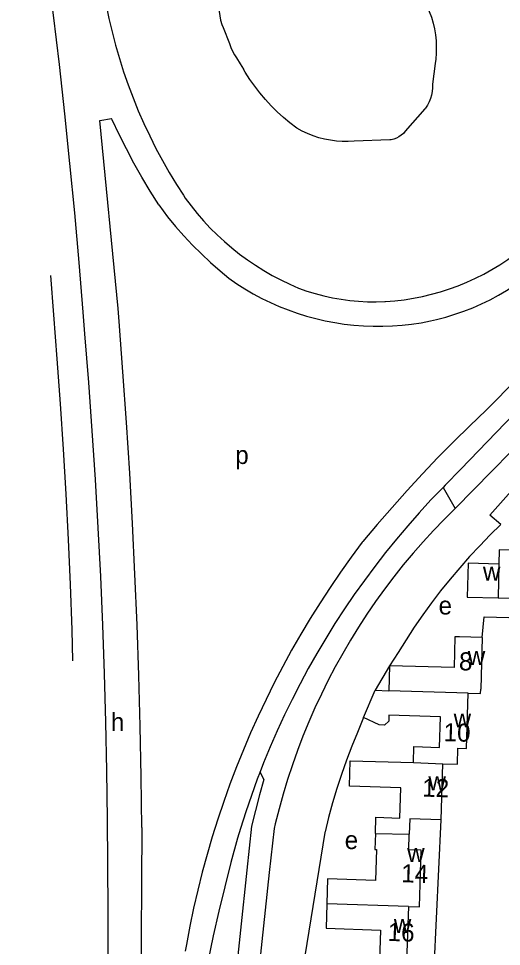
# Model space of a CAD drawing. Extents: x 161936 to 163647, y 386450 to 388633.
# Drawn here: x 162095.8 to 162202.6, y 388193.1 to 388398.4 of the extents above; entities that cross this region are included whole.
import ezdxf

# ---------------------------------------------------------------- set-up
doc = ezdxf.new("R2010")
doc.units = 0
for name, color, linetype in [('BLT_Basislijn', 7, 'Continuous'), ('BLT_Bebouwing', 7, 'Continuous'), ('BLT_Centroide', 7, 'Continuous'), ('BLT_Huisnummer', 7, 'Continuous'), ('BLT_Huisnummer_ tussenligend', 7, 'Continuous'), ('BLT_Onderverdeling_panden', 7, 'Continuous'), ('BLT_Vlakafsluiter', 7, 'Continuous')]:
    doc.layers.add(name, color=color, linetype=linetype)

msp = doc.modelspace()

# ---------------------------------------------------------------- linework, layer by layer
at = {"layer": 'BLT_Basislijn'}
for p, q in [((162141, 388396.47), (162142.43, 388392.92)), ((162187.94, 388388.47), (162187.36, 388383.94)), ((162185.66, 388378.42), (162181.32, 388373.49)), ((162177.93, 388371.59), (162170.03, 388371.27)), ((162132.22, 388359.34), (162132.63, 388358.72)), ((162126.77, 388357.19), (162128.69, 388354.54)), ((162215.83, 388321.82), (162193.61, 388298.7)), ((162206.52, 388295.81), (162200.04, 388288.54)), ((162202.51, 388286.46), (162200.04, 388288.54)), ((162150.04, 388230.05), (162149.21, 388231.74)), ((162187.39, 388181.56), (162189.26, 388221.14))]:
    msp.add_line(p, q, dxfattribs=at)
for points in [[(162095.76, 388453.7), (162097.45, 388442.82), (162099.06, 388431.93), (162100.59, 388421.03), (162102.04, 388410.11), (162103.42, 388399.19), (162104.71, 388388.26), (162105.92, 388377.32), (162107.06, 388366.37), (162108.11, 388355.41), (162109.09, 388344.45), (162109.98, 388333.48), (162110.35, 388328.63)], [(162114.11, 388407.51), (162114.58, 388404.48), (162115.12, 388401.46), (162115.74, 388398.46), (162116.44, 388395.47), (162117.21, 388392.51), (162118.07, 388389.56), (162119, 388386.64), (162120.01, 388383.75), (162121.09, 388380.88), (162122.24, 388378.04), (162123.47, 388375.23), (162124.78, 388372.45), (162126.15, 388369.71), (162127.6, 388367.01), (162129.11, 388364.35), (162130.7, 388361.72), (162132.22, 388359.34)], [(162184.87, 388403.57), (162185.53, 388402.42), (162186.13, 388401.22), (162186.65, 388399.99), (162187.1, 388398.73), (162187.48, 388397.44), (162187.77, 388396.14), (162187.99, 388394.82), (162188.13, 388393.49), (162188.19, 388392.15), (162188.17, 388390.81), (162188.07, 388389.48), (162187.94, 388388.47)], [(162140.1, 388400.92), (162140.14, 388399.96), (162140.26, 388399.01), (162140.46, 388398.07), (162140.74, 388397.15), (162141, 388396.47)], [(162142.43, 388392.92), (162142.73, 388392.05), (162143.09, 388391.21), (162143.54, 388390.4), (162143.97, 388389.74)], [(162143.97, 388389.74), (162144.81, 388388.42), (162145.5, 388387.2)], [(162157.32, 388374.18), (162155.82, 388375.33), (162154.38, 388376.54), (162152.99, 388377.81), (162151.66, 388379.14), (162150.38, 388380.52), (162149.16, 388381.96), (162148.01, 388383.44), (162146.92, 388384.98), (162145.89, 388386.56), (162145.5, 388387.2)], [(162187.36, 388383.94), (162187.36, 388383.12), (162187.29, 388382.31), (162187.13, 388381.51), (162186.9, 388380.73), (162186.6, 388379.97), (162186.22, 388379.25), (162185.77, 388378.57), (162185.66, 388378.42)], [(162117.77, 388334.29), (162113.78, 388375.91), (162116.32, 388376.3)], [(162126.77, 388357.19), (162124.88, 388360.23), (162123.05, 388363.31), (162121.3, 388366.43), (162119.61, 388369.59), (162118, 388372.79), (162116.45, 388376.02), (162116.32, 388376.3)], [(162170.03, 388371.27), (162168.71, 388371.2), (162167.4, 388371.22), (162166.08, 388371.31), (162164.78, 388371.49), (162163.49, 388371.74), (162162.21, 388372.07), (162160.96, 388372.48), (162159.73, 388372.96), (162158.54, 388373.52), (162157.32, 388374.18)], [(162181.32, 388373.49), (162180.91, 388373.02), (162180.45, 388372.61), (162179.94, 388372.25), (162179.38, 388371.97), (162178.8, 388371.76), (162178.19, 388371.62), (162177.93, 388371.59)], [(162132.63, 388358.72), (162133.92, 388356.98), (162135.28, 388355.29), (162136.7, 388353.66), (162138.18, 388352.08), (162139.71, 388350.55), (162141.3, 388349.09), (162142.95, 388347.68), (162144.64, 388346.33), (162146.39, 388345.05), (162148.18, 388343.83), (162150.01, 388342.68), (162151.88, 388341.6), (162153.8, 388340.59), (162155.75, 388339.65), (162157.71, 388338.79)], [(162188.26, 388331.81), (162190.3, 388332.36), (162192.31, 388332.98), (162194.3, 388333.68), (162196.26, 388334.45), (162198.18, 388335.3), (162200.08, 388336.22), (162201.94, 388337.21), (162203.76, 388338.27), (162205.54, 388339.4), (162207.27, 388340.59), (162208.96, 388341.86), (162210.6, 388343.18), (162212.18, 388344.56), (162213.72, 388346.01), (162215.2, 388347.51), (162216.62, 388349.07), (162217.97, 388350.68), (162219.27, 388352.34), (162220.51, 388354.04), (162221.67, 388355.8), (162222.77, 388357.59), (162223.13, 388358.21)], [(162128.69, 388354.54), (162130.49, 388352.41), (162132.34, 388350.33), (162134.26, 388348.3), (162136.23, 388346.34), (162138.26, 388344.42), (162140.34, 388342.57), (162142.27, 388340.95)], [(162176.97, 388335.8), (162179.03, 388335.96), (162181.08, 388336.21), (162183.12, 388336.53), (162185.15, 388336.94), (162187.16, 388337.42), (162189.15, 388337.98), (162191.12, 388338.61), (162193.06, 388339.32), (162194.97, 388340.11), (162196.85, 388340.97), (162198.69, 388341.9), (162200.5, 388342.9), (162202.27, 388343.97), (162203.99, 388345.11), (162205.67, 388346.32), (162207.31, 388347.58), (162208.89, 388348.91), (162210.42, 388350.3), (162211.89, 388351.75), (162213.31, 388353.26), (162214.66, 388354.82), (162215, 388355.23)], [(162232.95, 388353.08), (162230.38, 388349.25), (162227.73, 388345.47), (162225.02, 388341.73), (162222.25, 388338.04), (162219.41, 388334.4), (162216.51, 388330.81), (162213.55, 388327.27), (162210.53, 388323.78), (162207.44, 388320.35), (162204.3, 388316.96), (162201.1, 388313.64), (162199.25, 388311.77)], [(162102.8, 388341.59), (162103.5, 388332.85), (162104.21, 388323.12)], [(162142.27, 388340.95), (162144.03, 388339.74), (162145.83, 388338.6), (162147.68, 388337.52), (162149.56, 388336.52), (162151.49, 388335.59), (162153.44, 388334.73), (162155.43, 388333.95), (162157.44, 388333.24), (162159.48, 388332.6), (162161.54, 388332.05), (162163.62, 388331.57), (162165.72, 388331.16), (162167.83, 388330.84), (162169.95, 388330.6), (162172.08, 388330.43), (162174.21, 388330.35), (162176.35, 388330.35), (162178.48, 388330.42), (162180.61, 388330.58), (162182.73, 388330.82), (162184.85, 388331.13), (162186.94, 388331.52), (162188.26, 388331.81)], [(162157.71, 388338.79), (162159.55, 388338.14), (162161.41, 388337.56), (162163.3, 388337.07), (162165.2, 388336.65), (162167.12, 388336.3), (162169.05, 388336.04), (162170.99, 388335.86), (162172.94, 388335.76), (162174.89, 388335.73), (162176.84, 388335.79), (162176.97, 388335.8)], [(162123.02, 388219.45), (162122.88, 388230.66), (162122.66, 388241.86), (162122.35, 388253.07), (162121.97, 388264.27), (162121.51, 388275.47), (162120.97, 388286.66), (162120.35, 388297.86), (162119.64, 388309.04), (162118.86, 388320.22), (162118, 388331.4), (162117.77, 388334.29)], [(162110.35, 388328.63), (162111.21, 388317.91), (162112, 388307.18), (162112.7, 388296.45), (162113.32, 388285.71), (162113.87, 388274.97), (162114.33, 388264.23), (162114.71, 388253.48), (162115.01, 388242.73), (162115.24, 388231.97), (162115.38, 388221.22), (162115.44, 388211.56)], [(162104.21, 388323.12), (162104.96, 388313.14), (162105.63, 388303.15), (162106.23, 388293.16), (162106.74, 388283.17), (162107.17, 388273.17), (162107.52, 388263.17), (162107.71, 388256.27)], [(162222.9, 388321.82), (162212.82, 388310.85), (162192.34, 388290)], [(162199.25, 388311.77), (162195.63, 388308.32), (162192.07, 388304.83), (162188.57, 388301.27), (162185.12, 388297.66), (162181.73, 388293.99), (162178.4, 388290.27), (162175.13, 388286.5), (162171.92, 388282.68), (162171.81, 388282.54)], [(162193.61, 388298.7), (162190.14, 388295.16), (162189.68, 388294.69)], [(162189.68, 388294.69), (162187.02, 388291.9), (162184.41, 388289.07), (162181.86, 388286.17), (162179.37, 388283.23), (162176.94, 388280.24), (162174.58, 388277.19), (162172.28, 388274.1), (162170.05, 388270.96), (162167.88, 388267.78), (162165.77, 388264.55), (162163.74, 388261.27), (162161.77, 388257.96), (162159.87, 388254.6), (162158.05, 388251.21), (162156.29, 388247.78), (162154.6, 388244.32), (162152.99, 388240.82), (162151.45, 388237.28), (162149.98, 388233.72), (162149.21, 388231.74)], [(162192.34, 388290), (162189.93, 388287.61), (162187.58, 388285.17), (162185.29, 388282.67), (162183.06, 388280.12), (162180.89, 388277.52), (162178.77, 388274.86), (162176.73, 388272.16), (162174.75, 388269.41), (162172.83, 388266.61), (162170.98, 388263.77), (162169.2, 388260.89), (162167.48, 388257.96), (162165.84, 388255), (162164.26, 388251.99), (162162.76, 388248.96), (162161.33, 388245.88), (162159.97, 388242.78), (162158.68, 388239.64), (162157.47, 388236.47), (162156.34, 388233.28), (162155.28, 388230.05), (162154.3, 388226.81), (162153.39, 388223.54), (162152.56, 388220.26), (162152.31, 388219.18)], [(162202.51, 388286.46), (162200.14, 388284.15), (162197.82, 388281.78), (162195.57, 388279.36), (162193.37, 388276.88), (162191.24, 388274.35), (162189.16, 388271.76), (162187.15, 388269.13), (162185.2, 388266.45), (162183.32, 388263.73), (162181.51, 388260.96), (162179.76, 388258.15), (162177.84, 388255.22)], [(162171.81, 388282.54), (162169.38, 388279.26), (162167.02, 388275.93), (162164.71, 388272.56), (162162.48, 388269.14), (162160.32, 388265.68), (162158.22, 388262.18), (162156.19, 388258.63), (162154.23, 388255.05), (162152.34, 388251.43), (162150.52, 388247.77), (162148.77, 388244.08), (162147.1, 388240.35), (162145.5, 388236.59), (162143.98, 388232.81), (162142.52, 388228.99), (162141.15, 388225.14), (162139.85, 388221.27), (162138.62, 388217.38), (162137.48, 388213.46), (162136.4, 388209.52), (162135.41, 388205.55), (162134.49, 388201.57), (162133.66, 388197.58), (162132.9, 388193.56), (162132.63, 388192.02)], [(162198.35, 388261.47), (162198.76, 388266.06), (162253.12, 388264.6)], [(162177.84, 388255.22), (162174.69, 388249.79)], [(162172.1, 388243.78), (162170.74, 388240.46), (162169.49, 388237.39), (162168.32, 388234.29), (162167.22, 388231.17), (162166.19, 388228.02), (162165.24, 388224.85), (162164.37, 388221.65), (162163.58, 388218.44), (162163.54, 388218.29)], [(162149.21, 388231.74), (162148.59, 388230.12), (162147.27, 388226.5), (162146.03, 388222.85), (162144.87, 388219.18), (162144.22, 388217.04)], [(162150.04, 388230.05), (162149.07, 388226.64), (162148.17, 388223.21), (162147.34, 388219.73)], [(162123.02, 388219.45), (162122.84, 388182.82), (162121.93, 388145.11)], [(162147.34, 388219.73), (162146.25, 388210), (162140.63, 388156.86)], [(162152.31, 388219.18), (162151.22, 388209.46), (162146.96, 388169.2)], [(162163.54, 388218.29), (162158.65, 388188.26), (162155.9, 388168.3)], [(162144.22, 388217.04), (162142.76, 388211.68), (162141.37, 388206.3), (162140.07, 388200.9), (162138.83, 388195.48), (162137.68, 388190.05), (162136.61, 388184.59), (162135.61, 388179.13), (162134.69, 388173.65), (162133.86, 388168.16), (162133.1, 388162.65), (162132.81, 388160.38)], [(162115.44, 388211.56), (162115.51, 388200.66), (162115.5, 388189.76), (162115.4, 388178.86), (162115.23, 388167.97), (162114.98, 388157.07), (162114.65, 388146.18), (162114.24, 388135.28)]]:
    msp.add_lwpolyline(points, dxfattribs=at)
at = {"layer": 'BLT_Bebouwing'}
for p, q in [((162198.35, 388261.47), (162198.03, 388250)), ((162177.84, 388255.22), (162177.68, 388249.67)), ((162172.1, 388243.78), (162174.69, 388249.79)), ((162174.69, 388249.79), (162177.68, 388249.67)), ((162189.26, 388221.14), (162189.62, 388233.54))]:
    msp.add_line(p, q, dxfattribs=at)
for points in [[(162218.46, 388285.77), (162212.83, 388285.92), (162212.62, 388277.98), (162205.93, 388278.16), (162206, 388280.78), (162202.11, 388280.88), (162202.02, 388277.7)], [(162202.02, 388277.7), (162195.21, 388277.88), (162195.15, 388275.42), (162195.02, 388270.42), (162201.9, 388270.24)], [(162201.9, 388270.24), (162205.49, 388270.14), (162205.46, 388269.11), (162218.01, 388268.78), (162218.03, 388269.81)], [(162198.35, 388261.47), (162193.36, 388261.61), (162192.33, 388261.64), (162192.13, 388254.82), (162177.84, 388255.22)], [(162189.62, 388233.54), (162192.86, 388233.45), (162192.96, 388236.97), (162194.9, 388236.92), (162195.25, 388249.17)], [(162195.25, 388249.17), (162198, 388249.09), (162198.03, 388250)], [(162177.71, 388242.96), (162176.76, 388242.1), (162175.57, 388242.14), (162172.1, 388243.78)], [(162183.13, 388233.79), (162183.23, 388237.32), (162188.91, 388237.16), (162189.1, 388243.93), (162177.7, 388244.26), (162177.71, 388242.96)], [(162174.73, 388218.08), (162174.85, 388221.69), (162180.16, 388221.52), (162180.36, 388228.23), (162168.96, 388228.56), (162169.12, 388234.19), (162183.13, 388233.79)], [(162189.26, 388221.14), (162182.32, 388221.34), (162182.21, 388217.91)], [(162174.73, 388218.08), (162174.62, 388214.55), (162174.94, 388214.54), (162174.72, 388207.71), (162164.14, 388208.05), (162163.96, 388202.5)], [(162182.01, 388201.93), (162184.46, 388201.85), (162184.85, 388214.39), (162182.1, 388214.48), (162182.21, 388217.91)], [(162163.96, 388202.5), (162163.79, 388197.11), (162175.82, 388196.73), (162175.61, 388189.98)], [(162182.01, 388201.93), (162181.62, 388189.7), (162177.67, 388189.83)]]:
    msp.add_lwpolyline(points, dxfattribs=at)
at = {"layer": 'BLT_Onderverdeling_panden'}
for p, q in [((162202.02, 388277.7), (162201.9, 388270.24)), ((162195.25, 388249.17), (162177.68, 388249.67)), ((162183.13, 388233.79), (162189.62, 388233.54)), ((162174.73, 388218.08), (162182.21, 388217.91)), ((162182.01, 388201.93), (162163.96, 388202.5))]:
    msp.add_line(p, q, dxfattribs=at)
at = {"layer": 'BLT_Vlakafsluiter'}
msp.add_line((162189.68, 388294.69), (162192.34, 388290), dxfattribs=at)

# ---------------------------------------------------------------- texts
at = {"layer": 'BLT_Centroide'}
for s, p in [('p', (162143.71, 388299.86)), ('w', (162198.52, 388274.05)), ('e', (162188.7, 388266.55)), ('w', (162195.16, 388255.38)), ('h', (162116.18, 388240.76)), ('w', (162192.03, 388241.56)), ('w', (162186.45, 388227.66)), ('e', (162167.93, 388214.65)), ('w', (162181.74, 388211.78)), ('w', (162178.8, 388196.09))]:
    msp.add_text(s, height=4, dxfattribs=at).set_placement(p)
at = {"layer": 'BLT_Huisnummer'}
for s, rotation, p in [('8', 358.3672, (162193.17, 388254.23)), ('12', 358.3672, (162185.03, 388226.26)), ('14', 358.1845, (162180.39, 388207.32))]:
    msp.add_text(s, height=4, rotation=rotation, dxfattribs=at).set_placement(p)
at = {"layer": 'BLT_Huisnummer_ tussenligend'}
for s, rotation, p in [('10', 358.3604, (162189.77, 388238.54)), ('16', 358.1842, (162177.38, 388194.33))]:
    msp.add_text(s, height=4, rotation=rotation, dxfattribs=at).set_placement(p)

doc.saveas('drawing.dxf')
